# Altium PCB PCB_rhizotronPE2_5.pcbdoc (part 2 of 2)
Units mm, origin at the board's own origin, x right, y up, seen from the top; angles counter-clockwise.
Board outline 129.03 x 83.82 mm, 2 copper layers (Top Layer, Bottom Layer); 83 components, 240 nets, 494 pads, 295 vias.
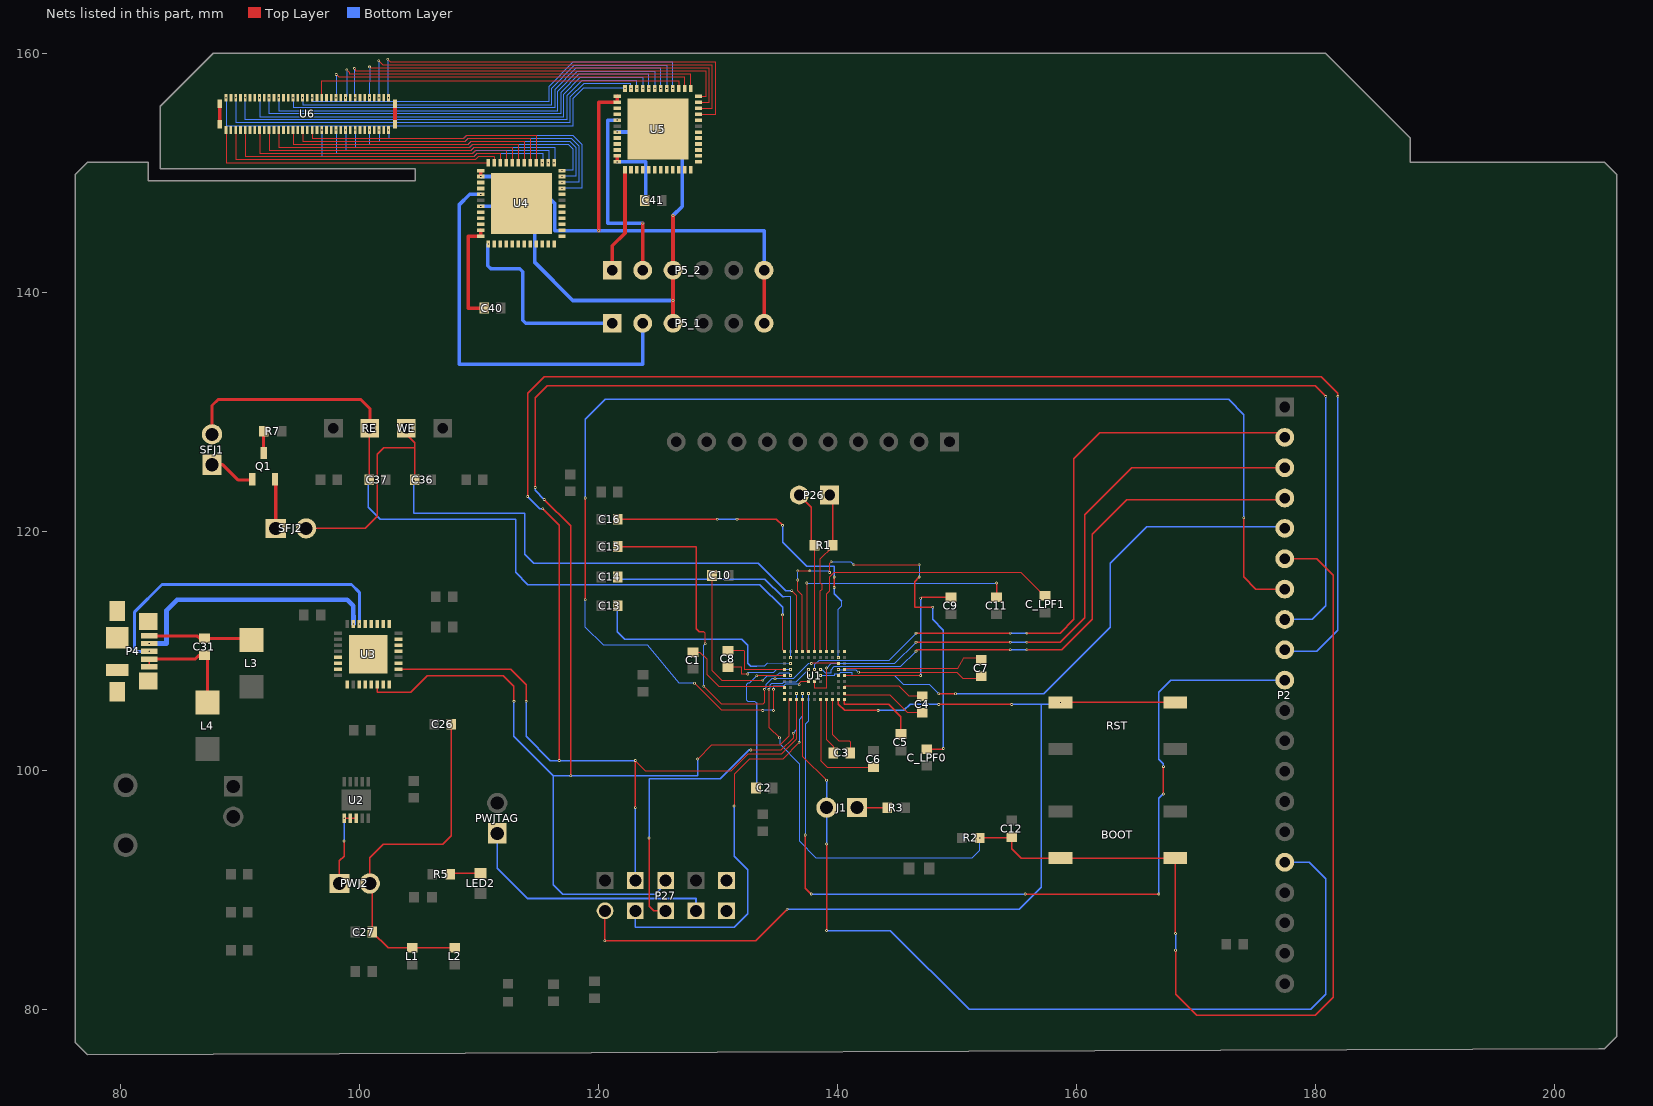
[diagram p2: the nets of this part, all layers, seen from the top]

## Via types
v1: diameter 0.225, hole 0.1, Top Layer to Bottom Layer, tented both sides, 295 vias

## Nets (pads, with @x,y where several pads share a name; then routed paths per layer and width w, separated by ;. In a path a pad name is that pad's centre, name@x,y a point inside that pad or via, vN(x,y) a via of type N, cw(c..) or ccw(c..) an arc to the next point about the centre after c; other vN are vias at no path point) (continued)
P0.5_SDA: P2.10 U1.H5 | length 74.4
  Top Layer w0.125: v1@137.311,94.591 137.311,90.146 v1@137.819,89.638 ; v1@155.726,89.638 v1@166.902,89.638 ; v1@167.283,98.02 v1@167.283,100.306
  Bottom Layer w0.1: v1@137.311,94.591 137.311,103.862 137.573,104.124 v1(137.573,106.426)
  Bottom Layer w0.125: v1@137.819,89.638 v1@155.726,89.638 ; v1@166.902,89.638 166.902,97.639 v1@167.283,98.02 ; v1@167.283,100.306 167.283,100.56 166.902,100.941 166.902,106.529 167.918,107.545 P2.10@177.443,107.545
  other v1: 137.819,89.638 155.726,89.638 166.902,89.638 137.311,94.591 167.283,98.02 167.283,100.306
P0.10_SOUT: P2.9 P27.4 U1.J3 U3.2 | length 179.8
  Top Layer w0.1: v1@123.087,100.814 123.976,99.925 131.088,99.925 132.485,101.322 135.279,101.322 136.572,102.615 U1.J3@136.572,105.927
  Top Layer w0.125: U3.2@103.275,108.454 112.653,108.454 113.943,107.164 v1@113.943,105.767 ; v1@114.07,122.912 114.07,131.548 115.467,132.945 180.491,132.945 181.888,131.548 v1@181.888,131.294 ; v1@115.34,121.896 116.708,120.528 v1@116.708,100.814 ; v1@123.087,96.877 v1@123.087,100.814
  Bottom Layer w0.125: v1@113.943,105.767 113.943,102.846 115.975,100.814 116.708,100.814 v1@123.087,100.814 ; v1@114.07,122.912 115.086,121.896 v1@115.34,121.896 ; P27.4@123.087,90.781 v1@123.087,96.877 ; P2.9@177.443,110.085 177.57,109.958 180.11,109.958 181.888,111.736 v1@181.888,131.294
  other v1: 123.087,96.877 116.708,100.814 123.087,100.814 113.943,105.767 115.34,121.896 114.07,122.912 181.888,131.294
P0.11_SIN: P2.8 P27.6 U1.J2 U3.30 | length 187.7
  Top Layer w0.1: v1@128.294,100.941 129.437,102.084 135.152,102.084 135.914,102.846 135.914,105.927 U1.J2@136.073,105.926
  Top Layer w0.125: U3.30@101.484,107.164 101.484,106.541 104.291,106.529 105.688,107.926 112.038,107.926 112.927,107.037 v1@112.927,105.767 ; v1@114.705,123.674 114.705,131.167 115.721,132.183 179.983,132.183 v1@180.872,131.294 ; v1@115.467,122.658 117.671,120.453 v1@117.671,99.544
  Bottom Layer w0.125: v1@112.927,105.767 112.927,102.846 116.229,99.544 ; v1@114.705,123.674 114.705,123.42 v1@115.467,122.658 ; P27.6@125.627,90.781 125.627,90.527 124.738,89.638 116.991,89.638 116.229,90.4 116.229,99.544 ; v1@128.294,100.941 128.294,99.544 117.671,99.544 116.229,99.544 ; P2.8@177.443,112.625 179.729,112.625 180.872,113.768 v1@180.872,131.294
  other v1: 117.671,99.544 128.294,100.941 112.927,105.767 115.467,122.658 114.705,123.674 180.872,131.294
P1.0: P2.7 U1.F5 | length 115.2
  Top Layer w0.1: v1(128.04,107.291) 130.326,105.005 v1(133.755,105.005) ; v1(134.644,105.005) v1@134.644,106.783 ; v1(136.803,107.164) 136.803,107.29 136.93,107.418 U1.F5@137.573,107.418
  Top Layer w0.125: v1@118.896,114.276 v1@118.896,122.785 ; v1@174.014,121.134 174.014,116.181 175.03,115.165 P2.7@177.443,115.165
  Bottom Layer w0.1: v1@118.896,114.276 118.896,111.99 120.42,110.466 124.103,110.466 126.77,107.291 127.024,107.291 v1(128.04,107.291) ; v1(133.755,105.005) v1(134.644,105.005) ; v1@134.644,106.783 134.644,107.037 135.479,107.037 135.631,107.189 v1@136.803,107.189
  Bottom Layer w0.125: v1@118.896,122.785 118.896,129.389 120.547,131.04 172.744,131.04 174.014,129.77 v1@174.014,121.134
  other v1: 134.644,106.774 118.896,114.276 174.014,121.134 118.896,122.785
P1.1: BOOT.1 BOOT.2 C12.2 P2.6 R2.1 U1.D5 | length 118.5
  Top Layer w0.1: v1@134.263,106.783 134.263,103.608 v1@135.152,102.719
  Top Layer w0.125: R2.1@151.907,94.337 154.521,94.337 C12.2@154.583,94.399 154.583,93.448 155.39,92.641 BOOT.2@158.673,92.641 BOOT.1@168.273,92.641 168.273,86.362 v1@168.299,86.336 ; v1@168.299,84.939 168.299,81.256 170.077,79.478 179.983,79.478 181.507,81.002 181.507,116.308 180.11,117.705 P2.6@177.443,117.705
  Bottom Layer w0.1: v1@134.263,106.783 134.39,106.909 134.39,107.164 134.517,107.291 135.406,107.291 135.533,107.418 136.549,107.418 v1(137.565,108.434) ; v1@135.152,102.719 135.152,102.211 136.803,100.56 136.803,94.083 138.2,92.686 151.281,92.686 151.916,93.321 v1@151.908,94.337
  Bottom Layer w0.125: v1@168.299,84.939 v1@168.299,86.336
  other v1: 168.299,84.939 168.299,86.336 151.907,94.337 135.152,102.719 134.263,106.774
P1.2_SCLK1: P2.5 U1.E7 | length 48.9
  Top Layer w0.125: v1@148.487,106.402 v1(149.884,106.402)
  Bottom Layer w0.1: v1@138.573,107.926 139.724,107.926 139.724,108.053 140.105,108.053 140.232,108.18 141.222,108.18 141.222,107.926 144.804,107.926 145.566,107.164 147.725,107.164 v1@148.487,106.402
  Bottom Layer w0.125: v1(149.884,106.402) 157.25,106.402 162.838,111.99 162.838,117.324 165.886,120.372 177.316,120.372 P2.5@177.443,120.245
  other v1: 148.487,106.402 138.573,107.926
P1.3_MOSI1: P2.4 U1.D7 | length 49.4
  Top Layer w0.125: v1@146.582,109.958 146.582,110.085 v1@154.456,110.085 ; v1@155.853,110.085 158.774,110.085 161.314,112.625 161.314,119.737 164.235,122.658 177.316,122.658 P2.4@177.443,122.785
  Bottom Layer w0.1: v1(138.581,108.434) 138.708,108.434 138.962,108.18 139.47,108.18 139.47,108.434 139.724,108.688 ; 139.724,108.689 145.312,108.689 ; 145.312,108.688 v1@146.582,109.958
  Bottom Layer w0.125: v1@154.456,110.085 v1@155.853,110.085
  other v1: 146.582,109.958 154.456,110.085 155.853,110.085
P1.4_MISO1: P2.3 U1.F6 | length 53.5
  Top Layer w0.1: U1.F6@138.073,107.426 138.073,106.91 139.089,106.91 v1(139.089,108.561)
  Top Layer w0.125: v1@146.582,110.72 v1@154.456,110.72 ; v1@155.853,110.72 158.647,110.72 160.679,112.752 160.679,121.388 164.616,125.325 P2.3@177.443,125.325
  Bottom Layer w0.1: v1(139.089,108.561) 139.475,108.947 144.809,108.947 v1@146.587,110.725
  Bottom Layer w0.125: v1@154.456,110.72 v1@155.853,110.72
  other v1: 146.582,110.72 154.456,110.72 155.853,110.72
P1.5_CS: P2.2 U1.D6 | length 55.9
  Top Layer w0.125: v1@146.582,111.482 v1@154.456,111.482 ; v1@155.853,111.482 158.647,111.482 159.79,112.625 159.79,126.087 161.949,128.246 177.062,128.246 P2.2@177.443,127.865
  Bottom Layer w0.1: v1(138.073,108.426) 138.073,108.815 138.421,109.163 144.296,109.163 ; 144.296,109.175 v1@146.582,111.482
  Bottom Layer w0.125: v1@154.456,111.482 v1@155.853,111.482
  other v1: 146.582,111.482 154.456,111.482 155.853,111.482
P2.4: J1.2 P2.16 U1.J4 | length 78.9
  Top Layer w0.1: U1.J4@137.072,105.927 137.072,101.18 v1@139.089,99.163
  Top Layer w0.125: v1@139.089,86.59 v1@139.089,93.829
  Bottom Layer w0.125: v1@139.089,86.59 144.423,86.59 151.027,79.986 179.602,79.986 180.872,81.256 180.872,90.908 179.475,92.305 P2.16@177.443,92.305 ; v1@139.089,93.829 J1.2@139.089,96.877 v1@139.089,99.163
  other v1: 139.089,86.59 139.089,93.829 139.089,99.163
P4_1: C31.2 L3.1 P4.1 | length 8.7
  Top Layer w0.254: P4.1@82.392,111.258 86.384,111.258 86.603,111.039 C31.2@87.019,111.039 90.809,111.039 L3.1@90.956,110.892
P4_4: C31.1 L4.1 P4.4 P4.5 | length 9.5
  Top Layer w0.125: P4.5@82.392,108.658 P4.4@82.392,109.308
  Top Layer w0.254: P4.4@82.392,109.308 86.257,109.308 86.588,109.639 C31.1@87.019,109.639 87.273,109.385 L4.1@87.273,105.685
P27_9: P27.9
P27_10: P27.10
PWJ2_2: C26.2 C27.2 L1.1 L2.1 PWJ2.2 | length 30.7
  Top Layer w0.125: C26.2@107.658,103.862 107.659,94.525 106.96,93.829 102.005,93.829 100.862,92.686 PWJ2.2@100.862,90.527 101.054,90.335 C27.2@101.054,86.463 102.386,85.131 L1.1@104.418,85.131 L2.1@107.974,85.131
PWJTAG_1: P27.7 PWJTAG.1 | length 21.6
  Bottom Layer w0.152: PWJTAG.1@111.53,94.718 111.53,91.797 114.07,89.257 128.167,89.257 P27.7@128.167,88.241
Q1_1: Q1.1 SFJ1.1 | length 3.9
  Top Layer w0.254: SFJ1.1@87.654,125.579 88.543,125.579 89.813,124.309 91.022,124.309 Q1.1@91.022,124.349
Q1_2: Q1.2 SFJ2.1 | length 4.1
  Top Layer w0.254: Q1.2@92.922,124.35 92.988,124.284 SFJ2.1@92.988,120.245
Q1_3: Q1.3 R7.1 | length 1.8
  Top Layer w0.254: Q1.3@91.972,126.553 R7.1@91.979,128.373
R3_2: J1.1 R3.2 | length 2.5
  Top Layer w0.125: J1.1@141.629,96.877 R3.2@144.177,96.877
R5_1: LED2.1 R5.1 | length 2.6
  Top Layer w0.125: R5.1@107.584,91.289 107.672,91.377 LED2.1@110.133,91.377
RE0: C37.1 RE.1 SFJ1.2 U1.A1 | length 69
  Top Layer w0.1: v1@135.406,113.006 135.406,110.093 U1.A1@135.573,109.926
  Top Layer w0.125: C37.1@100.797,124.309 100.797,128.562 RE.1@100.862,128.627
  Top Layer w0.254: SFJ1.2@87.654,128.119 87.654,130.532 88.162,131.04 100.1,131.04 100.862,130.278 RE.1@100.862,128.627
  Bottom Layer w0.125: v1@100.735,124.309 100.735,122.023 101.751,121.007 113.054,121.007 113.054,116.562 114.07,115.546 133.501,115.546 135.406,113.641 v1@135.406,113.006
  other v1: 135.406,113.006 100.735,124.309
RE1: U1.A11
RESET: P27.1 RST.1 RST.2 U1.J10 | length 85.3
  Top Layer w0.125: P27.1@120.547,88.241 120.523,88.217 v1(120.523,85.725) 133.144,85.725 v1@135.787,88.368 ; U1.J10@140.073,105.926 140.073,105.545 140.613,105.005 v1@143.407,105.005 ; v1@148.487,105.513 v1@154.583,105.513 ; v1(158.673,105.685) RST.2@168.273,105.685
  Bottom Layer w0.125: v1@135.787,88.368 155.218,88.368 157.054,90.204 157.054,105.513 ; v1@143.407,105.005 145.566,105.005 146.074,105.513 v1@148.487,105.513 ; v1@154.583,105.513 158.501,105.513 v1(158.673,105.685)
  other v1: 135.787,88.368 143.407,105.005 148.487,105.513 154.583,105.513
S$37411: 
SCLK: P5_1.3 P5_2.3 U4.19 U5.19 | length 43.9
  Top Layer w0.3: P5_1.3@126.238,137.414 P5_2.3@126.238,141.859 v1(126.238,146.431)
  Bottom Layer w0.3: v1(110.138,147.197) 114.681,147.197 114.681,142.494 117.856,139.319 v1(126.238,139.319) ; v1(121.568,153.42) 127,153.421 127,147.193 v1(126.238,146.431)
SE0: C36.1 SFJ2.2 U1.A3 WE.1 | length 63.9
  Top Layer w0.1: v1(136.168,115.038) 136.573,114.633 U1.A3@136.573,109.926
  Top Layer w0.125: SFJ2.2@95.528,120.245 100.481,120.245 101.497,121.261 101.497,126.468 102.015,126.986 104.606,126.986 ; WE.1@103.91,128.627 103.91,128.119 104.607,127.422 C36.1@104.607,124.309
  Bottom Layer w0.125: v1@104.545,124.309 104.545,121.515 113.816,121.515 113.816,118.086 114.578,117.324 133.374,117.324 135.66,115.038 v1(136.168,115.038)
  other v1: 104.545,124.256
SE1: U1.A9
SWCLK: P27.5 U1.H3 | length 29.6
  Top Layer w0.1: v1@132.739,101.703 135.279,101.703 136.325,102.719 136.325,103.07 v1@136.295,103.1
  Top Layer w0.125: v1@124.23,94.337 124.23,88.622 124.611,88.241 P27.5@125.627,88.241
  Bottom Layer w0.1: v1@136.295,103.1 136.573,103.378 v1(136.573,106.426)
  Bottom Layer w0.125: v1@124.23,94.337 124.23,99.29 130.199,99.29 132.612,101.703 v1@132.739,101.703
  other v1: 124.23,94.337 132.739,101.703 136.295,103.1
SWDIO: P27.3 U1.H4 | length 34.2
  Top Layer w0.1: v1@131.342,97.004 131.342,99.671 132.612,100.941 135.406,100.941 v1@136.803,102.338
  Bottom Layer w0.1: v1@136.803,102.338 136.803,104.243 137.073,104.513 v1(137.073,106.426)
  Bottom Layer w0.125: P27.3@123.087,88.241 123.087,86.844 131.342,86.844 132.485,87.987 132.485,91.67 131.342,92.813 v1@131.342,97.004
  other v1: 131.342,97.004 136.793,102.338
SYNC1: P5_1.2 U4.17 | length 34.3
  Bottom Layer w0.3: v1(110.138,148.197) 109.22,148.209 108.331,147.32 108.331,133.985 123.698,133.985 P5_1.2@123.698,137.414
SYNC2: P5_2.2 U5.17 | length 16.3
  Top Layer w0.3: P5_2.2@123.698,141.859 v1(123.698,145.796)
  Bottom Layer w0.3: v1(121.568,154.42) 120.777,154.42 120.777,145.796 v1(123.698,145.796)
TU4: P5_1.1 U4.25 | length 16.6
  Bottom Layer w0.3: v1(110.788,144.047) 110.744,144.003 110.744,142.24 110.998,141.986 113.411,141.986 113.665,141.732 113.665,137.668 113.919,137.414 P5_1.1@121.158,137.414
TU5: P5_2.1 U5.25 | length 8.8
  Top Layer w0.3: P5_2.1@121.158,141.859 121.158,143.891 122.217,144.95 U5.25@122.218,150.27
U1_A4: C_LPF0.2 U1.A4 | length 36.9
  Top Layer w0.1: v1(136.676,115.927) 136.676,115.038 137.073,114.64 U1.A4@137.073,109.926 ; v1(136.676,116.689) v1(137.692,116.689) ; v1(139.343,116.562) 139.343,117.324 v1(139.47,117.451) ; v1(141.375,117.197) v1(146.836,117.197)
  Top Layer w0.125: v1(146.836,116.181) 146.455,115.8 146.455,113.641 v1@147.979,113.641 ; C_LPF0.2@147.471,101.768 148.806,101.768 v1@148.868,101.83
  Bottom Layer w0.1: v1(136.676,115.927) v1(136.676,116.689) ; v1(137.692,116.689) 139.216,116.689 v1(139.343,116.562) ; v1(139.47,117.451) 141.121,117.451 v1(141.375,117.197) ; v1(146.836,116.181) v1(146.836,117.197)
  Bottom Layer w0.125: v1@147.979,113.641 147.979,112.625 148.868,111.736 v1@148.868,101.83
  other v1: 148.868,101.83 147.979,113.641
U1_A5: C11.2 U1.A5 | length 22.8
  Top Layer w0.1: v1(137.438,115.673) 137.438,109.925 U1.A5@137.572,109.925
  Top Layer w0.125: C11.2@153.313,114.468 v1@153.313,115.673
  Bottom Layer w0.1: v1(137.438,115.673) 153.186,115.673
  other v1: 153.313,115.673
U1_A6: P26.2 R1.1 U1.A6 | length 13.8
  Top Layer w0.1: 138.073,110.053 R1.1@138.073,118.975
  Top Layer w0.125: P26.2@136.803,123.039 137.819,122.023 137.819,118.848 R1.1@138.08,118.848
U1_A7: P26.1 R1.2 U1.A7 | length 13.7
  Top Layer w0.1: U1.A7@138.581,109.925 138.581,115.038 138.708,115.165 138.708,115.546 138.581,115.673 138.581,117.705 139.589,118.713 R1.2@139.588,118.848
  Top Layer w0.125: P26.1@139.343,123.039 139.588,122.793 R1.2@139.588,118.848
U1_A8: C_LPF1.2 U1.A8 | length 25.4
  Top Layer w0.1: U1.A8@139.089,109.925 139.089,114.784 139.343,115.038 139.343,116.181 139.724,116.562 155.345,116.562 157.311,114.596 C_LPF1.2@157.377,114.595
U1_D1: C8.1 U1.D1 | length 6.3
  Top Layer w0.1: C8.1@130.834,110.023 132.169,110.023 132.231,109.958 132.231,108.426 U1.D1@135.573,108.426
U1_D2: C8.2 U1.D2 | length 6
  Top Layer w0.1: C8.2@130.834,108.622 131.977,108.622 131.977,108.053 v1(132.485,108.053)
  Bottom Layer w0.1: v1(132.485,108.053) 132.485,108.18 134.644,108.18 134.89,108.426 v1(136.073,108.426)
U1_D10: C7.2 U1.D10 | length 12.5
  Top Layer w0.1: v1@141.771,108.2 150.011,108.2 ; 150.011,108.18 150.519,107.672 152.043,107.672 C7.2@152.043,107.86
  Bottom Layer w0.1: v1(140.073,108.426) 141.545,108.426 v1@141.771,108.2
  other v1: 141.771,108.2
U1_D11: C7.1 U1.D11 | length 12
  Top Layer w0.1: U1.D11@140.572,108.495 150.011,108.495 150.519,109.384 152.043,109.384 C7.1@152.043,109.323
U1_E1: C2.1 U1.E1 | length 12.9
  Top Layer w0.1: v1@133.247,107.926 U1.E1@135.573,107.926
  Bottom Layer w0.1: 133.247,105.64 133.028,105.767 132.485,105.767 132.358,105.894 132.358,107.164 132.485,107.291 132.612,107.291 v1@133.247,107.916
  Bottom Layer w0.125: v1@133.181,98.528 133.247,98.594 133.247,105.599
  other v1: 133.182,98.528 133.247,107.917
U1_E2: C10.2 U1.E2 | length 15.3
  Top Layer w0.1: C10.2@129.498,116.308 129.498,108.373 130.326,107.545 v1(133.755,107.545)
  Bottom Layer w0.1: v1(133.755,107.545) 134.136,107.926 134.898,107.926 135.152,108.18 135.914,108.18 136.041,108.053 136.041,107.958 v1@136.073,107.926
  other v1: 136.073,107.926
U1_E5: U1.E5
U1_E10: U1.E10
U1_E11: C9.2 U1.E11 | length 15.4
  Top Layer w0.1: U1.E11@140.573,107.926 v1@146.963,107.926
  Top Layer w0.125: v1@146.963,114.403 147.028,114.468 C9.2@149.503,114.468
  Bottom Layer w0.125: v1@146.963,107.926 v1@146.963,114.403
  other v1: 146.963,107.926 146.963,114.403
U1_G1: C1.2 U1.G1 | length 9.7
  Top Layer w0.1: C1.2@127.913,109.896 128.482,109.897 129.056,109.323 129.056,108.053 130.072,107.037 135.573,107.037 U1.G1@135.573,106.91
U1_G11: C4.1 U1.G11 | length 7
  Top Layer w0.1: U1.G11@140.572,106.91 140.572,107.037 145.185,107.037 146.008,106.214 C4.1@147.09,106.213
U1_H11: C4.2 U1.H11 | length 7.3
  Top Layer w0.1: U1.H11@140.572,106.402 140.572,106.275 144.423,106.275 145.886,104.812 C4.2@147.09,104.812
U1_J7: C6.1 U1.J7 | length 9.8
  Top Layer w0.1: 138.573,100.821 139.155,100.24 C6.1@143.026,100.24 ; 138.583,100.822 U1.J7@138.583,105.926
U1_J8: C3.2 U1.J8 | length 4.7
  Top Layer w0.1: U1.J8@139.073,105.926 139.073,102.592 139.659,102.006 C3.2@139.659,101.449
U1_J9: C3.1 U1.J9 | length 5.6
  Top Layer w0.1: U1.J9@139.573,105.926 139.574,102.996 140.105,102.465 140.994,102.465 141.06,102.399 C3.1@141.059,101.449
U1_J11: C5.2 U1.J11 | length 7
  Top Layer w0.125: U1.J11@140.572,105.927 140.572,105.513 144.296,105.513 145.312,104.497 C5.2@145.312,103.038
U2_1: PWJ2.1 U2.1 U2.2 U2.3 | length 6.6
  Top Layer w0.125: PWJ2.1@98.322,90.527 98.322,92.432 98.703,92.813 v1@98.703,94.083 ; U2.1@98.719,95.988 U2.2@99.219,95.988 U2.3@99.719,95.988
  Bottom Layer w0.125: v1@98.703,94.083 98.703,95.972 v1@98.719,95.988
  other v1: 98.703,94.083 98.719,95.988
U3_3: U3.3
U3_5: U3.5
U3_6: U3.6
U3_7: U3.7
U3_9: U3.9
U3_10: U3.10
U3_11: U3.11
U3_12: U3.12
U3_13: U3.13
U3_21: U3.21
U3_22: U3.22
U3_23: U3.23
U3_25: U3.25
U3_27: U3.27
U3_28: U3.28
U3_29: U3.29
U3_31: U3.31
U3_32: U3.32
U3_33: U3.33
U4_1: U4.1 U6.51 | length 20.6
  Bottom Layer w0.1: v1(98.831,153.585) 98.831,151.892 109.347,151.892 109.601,152.146 116.332,152.146 116.332,150.891 v1(116.288,150.847)
U4_2: U4.2 U6.47 | length 20.9
  Bottom Layer w0.1: v1(98.031,153.585) 98.031,151.638 109.474,151.638 109.728,151.892 115.824,151.892 115.824,150.883 v1(115.788,150.847)
U4_3: U4.3 U6.41 | length 21.6
  Bottom Layer w0.1: v1(96.831,153.585) 96.831,151.384 109.601,151.384 109.855,151.638 115.316,151.638 115.316,150.875 v1(115.288,150.847)
U4_4: U4.4 U6.37 | length 21.8
  Top Layer w0.1: U6.37@96.031,153.585 96.031,152.908 108.712,152.908 108.966,153.162 114.788,153.142 U4.4@114.788,150.847
U4_5: U4.5 U6.33 | length 22.1
  Top Layer w0.1: U6.33@95.231,153.585 95.231,152.654 108.839,152.654 109.093,152.908 114.288,152.896 U4.5@114.288,150.847
U4_6: U4.6 U6.29 | length 22.4
  Top Layer w0.1: U6.29@94.431,153.585 94.431,152.4 109.093,152.4 109.347,152.654 113.788,152.65 U4.6@113.788,150.847
U4_7: U4.7 U6.23 | length 23.1
  Top Layer w0.1: U6.23@93.231,153.585 93.231,152.146 109.22,152.146 109.474,152.4 113.288,152.396 U4.7@113.288,150.847
U4_8: U4.8 U6.19 | length 23.4
  Top Layer w0.1: U6.19@92.431,153.585 92.431,151.892 109.347,151.892 109.601,152.146 112.788,152.134 U4.8@112.788,150.847
U4_9: U4.9 U6.15 | length 23.7
  Top Layer w0.1: U6.15@91.631,153.585 91.631,151.638 109.474,151.638 109.728,151.892 112.288,151.872 U4.9@112.288,150.847
U4_10: U4.10 U6.9 | length 24.4
  Top Layer w0.1: U6.9@90.431,153.585 90.431,151.384 109.601,151.384 109.855,151.638 111.76,151.638 111.788,151.61 U4.10@111.788,150.847
U4_11: U4.11 U6.5 | length 24.7
  Top Layer w0.1: U6.5@89.631,153.585 89.631,151.13 109.728,151.13 109.982,151.384 111.252,151.384 111.288,151.348 U4.11@111.288,150.847
U4_12: U4.12 U6.1 | length 24.7
  Top Layer w0.1: U6.1@88.831,153.585 88.831,150.876 88.86,150.847 U4.12@110.788,150.847
U4_15: U4.15
U4_16: U4.16
U4_20: U4.20
U4_21: U4.21
U4_22: U4.22
U4_23: C40.1 U4.23 U4.24 | length 8.9
  Top Layer w0.3: U4.23@110.138,145.197 U4.24@110.138,144.697 109.093,144.697 109.093,138.684 C40.1@110.425,138.684
U4_26: U4.26
U4_27: U4.27
U4_28: U4.28
U4_29: U4.29
U4_30: U4.30
U4_31: U4.31
U4_32: U4.32
U4_33: U4.33
U4_34: U4.34
U4_35: U4.35
U4_36: U4.36
U4_37: U4.37
U4_38: U4.38
U4_39: U4.39
U4_40: U4.40
U4_41: U4.41
U4_42: U4.42
U4_44: U4.44
U4_45: U4.45 U6.69 | length 22.6
  Bottom Layer w0.1: v1(102.431,153.585) 102.431,152.908 108.712,152.908 108.966,153.162 117.856,153.162 118.618,152.4 118.618,148.717 v1(116.938,148.697)
U4_46: U4.46 U6.65 | length 22.5
  Bottom Layer w0.1: v1(101.631,153.585) 101.631,152.654 108.839,152.654 109.093,152.908 117.729,152.908 118.364,152.273 118.364,149.225 116.966,149.225 v1(116.938,149.197)
U4_47: U4.47 U6.61 | length 22.4
  Bottom Layer w0.1: v1(100.831,153.585) 100.831,152.4 109.093,152.4 109.347,152.654 117.602,152.654 118.11,152.146 118.11,149.733 116.974,149.733 v1(116.938,149.697)
U4_48: U4.48 U6.55 | length 22.6
  Bottom Layer w0.1: v1(99.631,153.585) 99.631,152.146 109.22,152.146 109.474,152.4 117.475,152.4 117.856,152.019 117.856,150.241 116.982,150.241 v1(116.938,150.197)
U4_49: U4.49
U5_1: U5.1 U6.52 | length 32.6
  Top Layer w0.1: v1(98.933,158.623) 99.187,158.369 99.187,158.242 127.719,158.242 U5.1@127.718,157.07
  Bottom Layer w0.1: v1(98.831,156.295) 98.933,156.397 v1(98.933,158.623)
U5_2: U5.2 U6.48 | length 32.1
  Top Layer w0.1: v1(98.044,158.242) 98.298,157.988 127.218,157.988 U5.2@127.218,157.07
  Bottom Layer w0.1: v1(98.031,156.295) v1(98.044,158.242)
U5_3: U5.3 U6.42 | length 32
  Top Layer w0.1: U6.42@96.831,156.295 96.83,157.734 126.718,157.734 U5.3@126.718,157.07
U5_4: U5.4 U6.38 | length 34.8
  Bottom Layer w0.1: v1(96.031,156.295) 96.03,155.956 115.824,155.956 115.824,157.226 117.856,159.258 126.218,159.258 v1(126.218,157.07)
U5_5: U5.5 U6.34 | length 35.2
  Bottom Layer w0.1: v1(95.231,156.295) 95.23,155.702 116.078,155.702 116.078,157.099 117.983,159.004 125.73,159.004 v1(125.718,157.07)
U5_6: U5.6 U6.30 | length 35.5
  Bottom Layer w0.1: v1(94.431,156.295) 94.488,156.238 94.488,155.448 116.332,155.448 116.332,156.972 118.11,158.75 125.218,158.75 v1(125.218,157.07)
U5_7: U5.7 U6.24 | length 36.3
  Bottom Layer w0.1: v1(93.231,156.295) 93.231,155.194 116.586,155.194 116.586,156.845 118.237,158.496 124.714,158.496 v1(124.718,157.07)
U5_8: U5.8 U6.20 | length 36.7
  Bottom Layer w0.1: v1(92.431,156.295) 92.456,154.94 116.84,154.94 116.84,156.718 118.364,158.242 124.219,158.242 v1(124.218,157.07)
U5_9: U5.9 U6.16 | length 37.1
  Bottom Layer w0.1: v1(91.631,156.295) 91.63,154.686 117.094,154.686 117.094,156.591 118.491,157.988 123.698,157.988 v1(123.718,157.07)
U5_10: U5.10 U6.10 | length 37.9
  Bottom Layer w0.1: v1(90.431,156.295) 90.424,154.432 117.348,154.432 117.348,156.464 118.618,157.734 123.218,157.734 v1(123.218,157.07)
U5_11: U5.11 U6.6 | length 38.2
  Bottom Layer w0.1: v1(89.631,156.295) 89.662,156.264 89.662,154.178 117.602,154.178 117.602,156.337 118.745,157.48 122.718,157.48 v1(122.718,157.07)
U5_12: U5.12 U6.2 | length 38.4
  Bottom Layer w0.1: v1(88.831,156.295) 88.9,156.226 88.9,153.924 117.856,153.924 117.856,156.21 118.716,157.07 v1(122.218,157.07)
U5_15: U5.15
U5_16: U5.16
U5_20: U5.20
U5_21: U5.21
U5_22: U5.22
U5_23: C41.1 U5.23 U5.24 | length 6.1
  Top Layer w0.3: v1(121.568,150.92) U5.23@121.568,151.42
  Bottom Layer w0.3: v1(121.568,150.92) 123.952,150.92 123.952,147.766 v1(123.887,147.701)
U5_26: U5.26
U5_27: U5.27
U5_28: U5.28
U5_29: U5.29
U5_30: U5.30
U5_31: U5.31
U5_32: U5.32
U5_33: U5.33
U5_34: U5.34
U5_35: U5.35
U5_36: U5.36
U5_37: U5.37
U5_38: U5.38
U5_39: U5.39
U5_40: U5.40
U5_41: U5.41
U5_42: U5.42
U5_44: U5.44
U5_45: U5.45 U6.70 | length 36.5
  Top Layer w0.1: v1(102.362,159.512) 102.616,159.258 129.794,159.258 129.794,154.92 U5.45@128.368,154.92
  Bottom Layer w0.1: v1(102.362,159.512) 102.362,156.364 v1(102.431,156.295)
U5_46: U5.46 U6.66 | length 36
  Top Layer w0.1: v1(101.6,159.385) 101.981,159.004 129.54,159.004 129.54,155.42 U5.46@128.368,155.42
  Bottom Layer w0.1: v1(101.6,159.385) 101.6,156.326 v1(101.631,156.295)
U5_47: U5.47 U6.62 | length 34.8
  Top Layer w0.1: v1(100.838,158.877) 100.965,158.75 129.286,158.75 129.286,155.956 129.25,155.92 U5.47@128.368,155.92
  Bottom Layer w0.1: v1(100.831,156.295) v1(100.838,158.877)
U5_48: U5.48 U6.56 | length 34.9
  Top Layer w0.1: v1(99.568,158.75) 99.695,158.623 99.695,158.496 129.032,158.496 129.032,156.421 U5.48@128.368,156.42
  Bottom Layer w0.1: v1(99.568,158.75) 99.568,156.358 v1(99.631,156.295)
U5_49: U5.49
U6_3: U6.3
U6_4: U6.4
U6_7: U6.7
U6_8: U6.8
U6_11: U6.11
U6_12: U6.12
U6_13: U6.13
U6_14: U6.14
U6_17: U6.17
U6_18: U6.18
U6_21: U6.21
U6_22: U6.22
U6_25: U6.25
U6_26: U6.26
U6_27: U6.27
U6_28: U6.28
U6_31: U6.31
U6_32: U6.32
U6_35: U6.35
U6_36: U6.36
U6_39: U6.39
U6_40: U6.40
U6_43: U6.43
U6_44: U6.44
U6_45: U6.45
U6_46: U6.46
U6_49: U6.49
U6_50: U6.50
U6_53: U6.53
U6_54: U6.54
U6_57: U6.57
U6_58: U6.58
U6_59: U6.59
U6_60: U6.60
U6_63: U6.63
U6_64: U6.64
U6_67: U6.67
U6_68: U6.68
U6_SHLD: U6.71 U6.72 U6.73 U6.SHLD | length 3.4
  Top Layer w0.3: U6.73@88.296,154.08 U6.SHLD@88.296,155.8 ; U6.71@102.966,154.08 U6.72@102.966,155.8
USBD+: P4.3 U3.14 | length 27.2
  Bottom Layer w0.25: v1@82.393,109.957 81.176,109.957 81.176,113.259 83.462,115.545 99.337,115.545 99.985,114.899 v1@99.985,112.243
  other v1: 82.392,109.958 99.985,112.244 99.985,112.244
USBD-: P4.2 U3.15 | length 22
  Bottom Layer w0.4: v1@82.391,110.608 83.844,110.608 83.844,113.387 84.733,114.276 98.957,114.276 99.465,113.768 v1@99.485,112.244
  other v1: 82.392,110.608 99.485,112.244
VBIAS0: C13.2 U1.C2 | length 18.9
  Bottom Layer w0.1: 133.247,108.688 133.882,108.688 134.136,108.942 v1(136.073,108.926)
  Bottom Layer w0.125: v1@121.628,113.768 121.563,113.703 121.563,111.609 122.198,110.974 131.977,110.974 132.485,110.466 132.485,108.942 132.739,108.688 133.247,108.688
  other v1: 121.628,113.768
VBIAS1: C15.2 U1.C10 | length 33
  Top Layer w0.1: v1(128.802,107.037) 130.326,105.513 133.755,105.513 133.882,105.64 v1@133.882,106.783 ; 128.802,111.609 128.929,111.482 v1(128.929,110.593) ; v1(137.819,108.942) U1.C10@140.074,108.942
  Top Layer w0.125: C15.2@121.628,118.721 128.167,118.721 128.167,111.863 128.421,111.609 128.802,111.609
  Bottom Layer w0.1: v1(128.802,107.037) 128.802,110.466 v1(128.929,110.593) ; v1@133.882,106.783 134.009,106.909 134.009,107.164 134.507,107.662 134.771,107.662 136.295,107.662 137.565,108.932 v1(137.819,108.942)
  other v1: 133.882,106.774 134.771,107.662
VDD: P5_1.6 P5_2.6 U4.13 U4.14 U5.13 U5.14 | length 48
  Top Layer w0.3: v1(110.138,149.697) U4.13@110.138,150.197 ; v1(120.015,145.161) 120.015,155.92 U5.14@121.568,155.92 U5.13@121.568,156.42 ; P5_1.6@133.858,137.414 P5_2.6@133.858,141.859
  Bottom Layer w0.3: v1(110.138,149.697) 114.082,149.697 116.332,147.447 116.332,145.161 133.858,145.161 P5_2.6@133.858,141.859
VZERO0: C14.2 U1.B2 | length 20.2
  Bottom Layer w0.1: 135.533,114.53 136.073,114.53 v1(136.073,109.426)
  Bottom Layer w0.125: v1@121.629,116.181 121.802,116.008 133.928,116.008 135.406,114.53 135.533,114.53
  other v1: 121.628,116.181
VZERO1: C16.2 U1.B10 | length 28.6
  Top Layer w0.125: C16.2@121.628,121.007 v1@129.945,121.007 ; v1@131.596,121.007 134.898,121.007 v1(135.406,120.499) ; v1(139.724,115.292) v1@139.724,116.181
  Bottom Layer w0.1: v1(140.073,109.426) 140.073,113.482 140.359,113.768 140.359,114.149
  Bottom Layer w0.125: v1@129.945,121.007 v1@131.596,121.007 ; v1(135.406,120.499) 135.406,119.102 137.438,117.07 139.724,117.07 v1@139.724,116.181 ; v1(139.724,115.292) 139.724,114.783 140.359,114.149
  other v1: 139.724,116.181 129.945,121.007 131.596,121.007
XTALI: U1.H1
XTALO: U1.J1
"": P4.6 P4.7 P4.8 P4.9 P4.10 P4.GND

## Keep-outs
Board Outline Layer:
  lines w0.1 net S$37411: 82.296,150.876 82.296,149.352 104.648,149.352 104.648,150.368 83.312,150.368 83.312,150.876 83.312,151.242 83.312,151.47 83.312,152.908 83.312,155.575 87.757,160.02 90.424,160.02 180.848,160.02 187.96,152.908 187.96,150.876 204.216,150.876 205.232,149.86 ; 82.299,150.876 77.216,150.876 76.2,149.86 ; 76.2,149.86 76.2,77.216 77.216,76.2 203.708,76.708 204.216,76.708 205.232,77.724 205.232,149.86 ; 76.2,149.86 76.2,149.86 ; 205.232,149.86 205.232,149.86

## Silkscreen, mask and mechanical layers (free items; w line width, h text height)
Mechanical Layer:
  circle w0.005 net "": c78.486,79.248 r1.016
  circle w0.005 net "": c78.486,148.248 r1.016
  circle w0.005 net "": c202.486,148.248 r1.016
  circle w0.005 net "": c202.486,79.248 r1.016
